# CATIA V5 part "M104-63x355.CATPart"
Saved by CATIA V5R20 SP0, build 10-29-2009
Part number: M104-63x355
Source: Unknown
Bounding box of the stored display mesh (mm): x -31.459 to 31.459, y -31.459 to 31.459, z 0 to 355
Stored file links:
  C:\Users\Utente\Desktop\IO LAVORO\3D X SITO CF\X SITO\M104\M104-63x355.CATPart
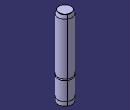
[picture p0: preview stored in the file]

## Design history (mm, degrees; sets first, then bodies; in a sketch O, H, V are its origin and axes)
Body1 (main body)
  Solid1 "PartBody": solid without history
